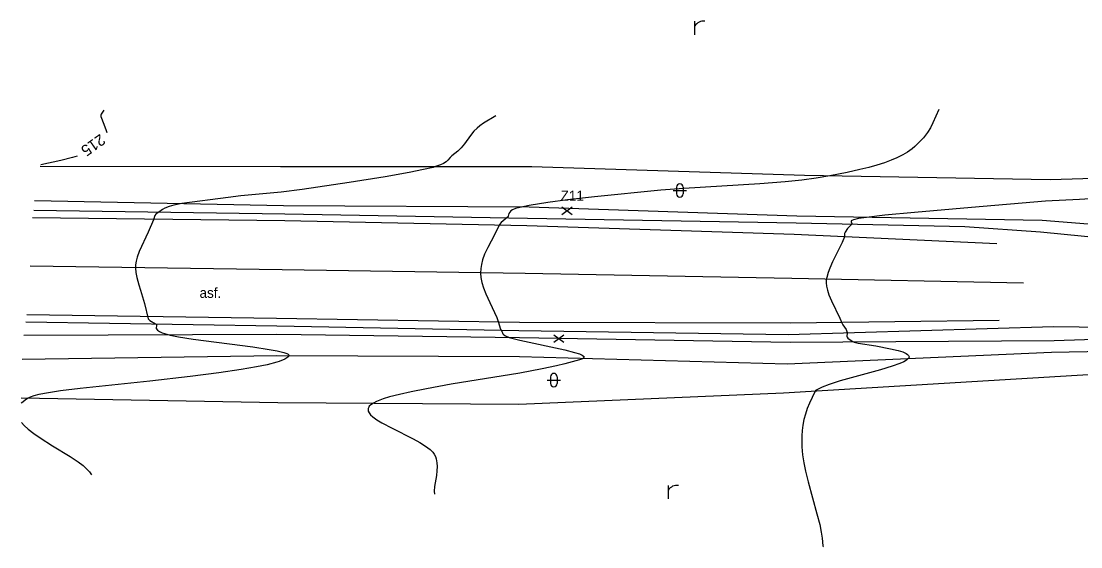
# Model space of a CAD drawing. Extents: x -593772 to -592667, y -1183541 to -1183371.
# Drawn here: x -593771.8 to -593692.9, y -1183410.3 to -1183371.1 of the extents above; entities that cross this region are included whole.
import ezdxf

# ---------------------------------------------------------------- set-up
doc = ezdxf.new("R2010")
doc.units = 0
for name, color, linetype in [('bez obruby', 7, 'Continuous'), ('hlavni vrstevnice', 7, 'Continuous'), ('popis ploch', 7, 'Continuous'), ('svisle dopravni znaceni', 7, 'Continuous'), ('terenni hrany', 7, 'Continuous'), ('vodorovne dopravni znaceni', 7, 'Continuous'), ('vrstevnice', 7, 'Continuous')]:
    doc.layers.add(name, color=color, linetype=linetype)

msp = doc.modelspace()

# ---------------------------------------------------------------- linework, layer by layer
at = {"layer": 'bez obruby'}
for p, q in [((-593752.18, -1183385.49), (-593770.88, -1183385.22)), ((-593734.08, -1183385.82), (-593752.18, -1183385.49)), ((-593714.07, -1183386.17), (-593734.08, -1183385.82)), ((-593701.52, -1183386.44), (-593714.07, -1183386.17)), ((-593695.87, -1183386.84), (-593701.52, -1183386.44)), ((-593688.93, -1183387.52), (-593695.87, -1183386.84)), ((-593752.76, -1183393.84), (-593771.46, -1183393.55)), ((-593734.75, -1183394.2), (-593752.76, -1183393.84)), ((-593694.9, -1183393.91), (-593714.68, -1183394.5)), ((-593678.82, -1183394.05), (-593694.9, -1183393.91)), ((-593714.68, -1183394.5), (-593734.75, -1183394.2))]:
    msp.add_line(p, q, dxfattribs=at)
at = {"layer": 'hlavni vrstevnice'}
for points in [[(-593765.643, -1183377.754), (-593765.843, -1183378.037), (-593765.873, -1183378.123), (-593765.874, -1183378.214), (-593765.836, -1183378.355), (-593765.707, -1183378.662), (-593765.5, -1183379.195), (-593765.441, -1183379.411)], [(-593767.646, -1183381.184), (-593767.992, -1183381.282), (-593768.866, -1183381.496), (-593770.357, -1183381.812)]]:
    msp.add_lwpolyline(points, dxfattribs=at)
at = {"layer": 'popis ploch'}
for p, q in [((-593721.63, -1183372.12), (-593721.63, -1183371.12)), ((-593723.24, -1183383.74), (-593722.24, -1183383.74)), ((-593722.99, -1183383.49), (-593722.99, -1183383.99)), ((-593722.49, -1183383.49), (-593722.49, -1183383.99)), ((-593732.63, -1183397.87), (-593731.63, -1183397.87)), ((-593732.38, -1183397.62), (-593732.38, -1183398.12)), ((-593731.88, -1183397.62), (-593731.88, -1183398.12)), ((-593723.6, -1183406.73), (-593723.6, -1183405.73))]:
    msp.add_line(p, q, dxfattribs=at)
for centre, radius, start, end in [((-593720.993, -1183371.857), 0.746, 81.32683, 148.70696), ((-593722.741, -1183383.49), 0.25, 0, 180), ((-593722.741, -1183383.99), 0.25, 180, 0), ((-593732.131, -1183397.62), 0.25, 0, 180), ((-593732.131, -1183398.12), 0.25, 180, 0), ((-593722.963, -1183406.468), 0.746, 81.32683, 148.70696)]:
    msp.add_arc(centre, radius, start, end, dxfattribs=at)
at = {"layer": 'svisle dopravni znaceni'}
for p, q in [((-593731.525, -1183385.521), (-593730.775, -1183384.958)), ((-593731.525, -1183384.958), (-593730.775, -1183385.521)), ((-593732.125, -1183395.051), (-593731.375, -1183394.488)), ((-593732.125, -1183394.488), (-593731.375, -1183395.051))]:
    msp.add_line(p, q, dxfattribs=at)
at = {"layer": 'terenni hrany'}
for p, q in [((-593752.49, -1183381.97), (-593770.39, -1183381.95)), ((-593733.78, -1183381.98), (-593752.49, -1183381.97)), ((-593713.46, -1183382.62), (-593733.78, -1183381.98)), ((-593695.15, -1183382.93), (-593713.46, -1183382.62)), ((-593678.75, -1183382.47), (-593695.15, -1183382.93)), ((-593752.26, -1183384.88), (-593770.82, -1183384.5)), ((-593733.97, -1183384.97), (-593752.26, -1183384.88)), ((-593714.04, -1183385.64), (-593733.97, -1183384.97)), ((-593695.76, -1183385.98), (-593714.04, -1183385.64)), ((-593678.56, -1183387.34), (-593695.76, -1183385.98)), ((-593752.76, -1183394.47), (-593771.61, -1183394.56)), ((-593734.7, -1183394.71), (-593752.76, -1183394.47)), ((-593714.52, -1183395.08), (-593734.7, -1183394.71)), ((-593678.83, -1183394.43), (-593694.86, -1183394.94)), ((-593694.86, -1183394.94), (-593714.52, -1183395.08)), ((-593678.91, -1183395.57), (-593695.06, -1183395.81)), ((-593752.77, -1183396.07), (-593771.73, -1183396.33)), ((-593734.68, -1183396.15), (-593752.77, -1183396.07)), ((-593714.74, -1183396.69), (-593734.68, -1183396.15)), ((-593695.06, -1183395.81), (-593714.74, -1183396.69)), ((-593684.31, -1183397), (-593715.02, -1183398.85)), ((-593752.7, -1183399.56), (-593771.81, -1183399.21)), ((-593734.75, -1183399.68), (-593752.7, -1183399.56)), ((-593715.02, -1183398.85), (-593734.75, -1183399.68))]:
    msp.add_line(p, q, dxfattribs=at)
at = {"layer": 'vodorovne dopravni znaceni'}
for p, q in [((-593752.16, -1183386.01), (-593770.97, -1183385.78)), ((-593734.14, -1183386.36), (-593752.16, -1183386.01)), ((-593714.22, -1183387.02), (-593734.14, -1183386.36)), ((-593699.14, -1183387.71), (-593714.22, -1183387.02)), ((-593752.37, -1183389.65), (-593771.15, -1183389.39)), ((-593734.26, -1183389.93), (-593752.37, -1183389.65)), ((-593714.41, -1183390.29), (-593734.26, -1183389.93)), ((-593697.15, -1183390.64), (-593714.41, -1183390.29)), ((-593752.78, -1183393.27), (-593771.4, -1183393.01)), ((-593734.7, -1183393.59), (-593752.78, -1183393.27)), ((-593714.49, -1183393.63), (-593734.7, -1183393.59)), ((-593698.96, -1183393.44), (-593714.49, -1183393.63))]:
    msp.add_line(p, q, dxfattribs=at)
at = {"layer": 'vrstevnice'}
for points in [[(-593736.445, -1183378.178), (-593737.379, -1183378.725), (-593737.649, -1183378.912), (-593737.847, -1183379.078), (-593738.091, -1183379.323), (-593738.339, -1183379.633), (-593738.779, -1183380.25), (-593739.038, -1183380.555), (-593739.29, -1183380.799), (-593739.723, -1183381.149), (-593739.847, -1183381.272), (-593740.021, -1183381.481), (-593740.159, -1183381.609), (-593740.343, -1183381.727), (-593740.572, -1183381.832), (-593740.941, -1183381.958), (-593741.128, -1183382.01), (-593741.829, -1183382.178), (-593742.915, -1183382.398), (-593744.693, -1183382.713), (-593747.378, -1183383.141), (-593750.867, -1183383.654), (-593752.444, -1183383.866), (-593755.439, -1183384.139), (-593756.385, -1183384.247), (-593759.846, -1183384.717), (-593760.433, -1183384.822), (-593760.779, -1183384.919), (-593761.1, -1183385.049), (-593761.271, -1183385.151), (-593761.56, -1183385.363), (-593761.78, -1183385.504), (-593761.861, -1183385.597), (-593761.962, -1183385.912), (-593762.361, -1183386.846), (-593763.014, -1183388.293), (-593763.165, -1183388.698), (-593763.246, -1183388.993), (-593763.294, -1183389.29), (-593763.303, -1183389.532), (-593763.277, -1183389.839), (-593763.203, -1183390.214), (-593763.039, -1183390.78), (-593762.919, -1183391.161), (-593762.63, -1183392.168), (-593762.339, -1183393.294), (-593762.288, -1183393.372), (-593762.232, -1183393.42), (-593761.798, -1183393.668), (-593761.756, -1183393.707), (-593761.727, -1183393.76), (-593761.73, -1183393.833), (-593761.764, -1183393.969), (-593761.744, -1183394.035), (-593761.661, -1183394.138), (-593761.519, -1183394.244), (-593761.297, -1183394.349), (-593760.972, -1183394.456), (-593760.718, -1183394.519), (-593760.09, -1183394.642), (-593758.99, -1183394.811), (-593754.559, -1183395.391), (-593753.328, -1183395.581), (-593752.75, -1183395.69), (-593752.236, -1183395.813), (-593752.03, -1183395.885), (-593751.926, -1183395.936), (-593751.862, -1183395.988), (-593751.84, -1183396.037), (-593751.845, -1183396.061), (-593751.94, -1183396.166), (-593752.161, -1183396.306), (-593752.585, -1183396.476), (-593752.757, -1183396.536), (-593753.484, -1183396.723), (-593754.29, -1183396.889), (-593755.417, -1183397.083), (-593757.098, -1183397.328), (-593759.219, -1183397.597), (-593762.224, -1183397.944), (-593767.405, -1183398.489), (-593768.871, -1183398.674), (-593769.786, -1183398.817), (-593770.507, -1183398.958), (-593770.873, -1183399.053), (-593771.145, -1183399.147), (-593771.285, -1183399.212), (-593771.496, -1183399.351), (-593771.695, -1183399.507), (-593771.804, -1183399.602)], [(-593703.459, -1183377.701), (-593703.888, -1183378.68), (-593704.081, -1183379.054), (-593704.306, -1183379.416), (-593704.602, -1183379.8), (-593705.007, -1183380.242), (-593705.229, -1183380.45), (-593705.441, -1183380.626), (-593705.784, -1183380.869), (-593706.139, -1183381.08), (-593706.569, -1183381.296), (-593706.997, -1183381.477), (-593707.503, -1183381.663), (-593708.061, -1183381.842), (-593708.671, -1183382.015), (-593709.331, -1183382.182), (-593710.276, -1183382.394), (-593711.578, -1183382.655), (-593712.579, -1183382.821), (-593713.645, -1183382.967), (-593714.891, -1183383.09), (-593716.782, -1183383.233), (-593722.438, -1183383.578), (-593724.166, -1183383.72), (-593729.096, -1183384.208), (-593731.113, -1183384.441), (-593732.574, -1183384.638), (-593733.98, -1183384.867), (-593734.666, -1183385.001), (-593734.988, -1183385.088), (-593735.205, -1183385.176), (-593735.339, -1183385.26), (-593735.419, -1183385.346), (-593735.473, -1183385.459), (-593735.531, -1183385.658), (-593735.597, -1183385.757), (-593736.062, -1183386.133), (-593736.172, -1183386.265), (-593736.563, -1183387.037), (-593737.057, -1183387.984), (-593737.286, -1183388.493), (-593737.433, -1183388.896), (-593737.526, -1183389.244), (-593737.572, -1183389.544), (-593737.584, -1183389.91), (-593737.558, -1183390.221), (-593737.484, -1183390.601), (-593737.371, -1183390.986), (-593737.199, -1183391.437), (-593736.902, -1183392.093), (-593736.384, -1183393.206), (-593736.248, -1183393.567), (-593736.127, -1183394.01), (-593736.071, -1183394.134), (-593736.016, -1183394.227), (-593735.938, -1183394.414), (-593735.865, -1183394.498), (-593735.736, -1183394.583), (-593735.455, -1183394.694), (-593735.25, -1183394.754), (-593734.661, -1183394.895), (-593731.303, -1183395.62), (-593730.591, -1183395.806), (-593730.222, -1183395.927), (-593730.009, -1183396.025), (-593729.916, -1183396.091), (-593729.883, -1183396.141), (-593729.885, -1183396.189), (-593729.921, -1183396.235), (-593729.992, -1183396.279), (-593730.223, -1183396.366), (-593731.304, -1183396.656), (-593731.928, -1183396.815), (-593732.991, -1183397.042), (-593734.654, -1183397.349), (-593739.777, -1183398.186), (-593741.614, -1183398.515), (-593742.77, -1183398.746), (-593743.623, -1183398.937), (-593744.366, -1183399.13), (-593744.855, -1183399.281), (-593745.345, -1183399.47), (-593745.568, -1183399.581), (-593745.762, -1183399.71), (-593745.878, -1183399.823), (-593745.918, -1183399.879), (-593745.969, -1183400), (-593745.972, -1183400.128), (-593745.956, -1183400.19), (-593745.892, -1183400.323), (-593745.781, -1183400.463), (-593745.622, -1183400.61), (-593745.323, -1183400.828), (-593744.953, -1183401.054), (-593744.181, -1183401.464), (-593742.607, -1183402.251), (-593742.104, -1183402.527), (-593741.68, -1183402.796), (-593741.348, -1183403.056), (-593741.151, -1183403.257), (-593741.038, -1183403.407), (-593740.949, -1183403.574), (-593740.897, -1183403.733), (-593740.844, -1183404.046), (-593740.826, -1183404.305), (-593740.838, -1183404.639), (-593740.88, -1183404.987), (-593741.022, -1183405.811), (-593741.047, -1183406.147), (-593741.027, -1183406.39)], [(-593691.791, -1183384.34), (-593692.965, -1183384.416), (-593695.51, -1183384.54), (-593701.027, -1183384.993), (-593705.272, -1183385.366), (-593707.465, -1183385.587), (-593708.827, -1183385.744), (-593709.422, -1183385.833), (-593709.812, -1183385.918), (-593709.929, -1183385.966), (-593709.972, -1183386.008), (-593709.978, -1183386.061), (-593709.928, -1183386.196), (-593709.938, -1183386.24), (-593710.243, -1183386.576), (-593710.434, -1183386.846), (-593710.466, -1183386.95), (-593710.479, -1183387.181), (-593710.657, -1183387.612), (-593711.379, -1183389.067), (-593711.57, -1183389.515), (-593711.687, -1183389.846), (-593711.805, -1183390.211), (-593711.835, -1183390.367), (-593711.844, -1183390.614), (-593711.814, -1183390.872), (-593711.75, -1183391.158), (-593711.638, -1183391.504), (-593711.443, -1183391.971), (-593710.825, -1183393.255), (-593710.684, -1183393.593), (-593710.593, -1183393.761), (-593710.362, -1183394.111), (-593710.269, -1183394.328), (-593710.271, -1183394.372), (-593710.311, -1183394.589), (-593710.291, -1183394.676), (-593710.237, -1183394.752), (-593709.915, -1183394.978), (-593709.749, -1183395.05), (-593709.47, -1183395.114), (-593708.134, -1183395.323), (-593707.041, -1183395.532), (-593706.488, -1183395.664), (-593706.138, -1183395.772), (-593705.894, -1183395.879), (-593705.774, -1183395.958), (-593705.699, -1183396.039), (-593705.676, -1183396.092), (-593705.671, -1183396.146), (-593705.695, -1183396.226), (-593705.751, -1183396.299), (-593705.848, -1183396.381), (-593706.062, -1183396.506), (-593706.361, -1183396.638), (-593706.928, -1183396.843), (-593707.799, -1183397.108), (-593710.788, -1183397.931), (-593711.631, -1183398.195), (-593712.14, -1183398.391), (-593712.53, -1183398.588), (-593712.629, -1183398.66), (-593712.691, -1183398.74), (-593713.09, -1183399.589), (-593713.257, -1183400.001), (-593713.393, -1183400.411), (-593713.501, -1183400.819), (-593713.58, -1183401.225), (-593713.632, -1183401.63), (-593713.661, -1183402.034), (-593713.667, -1183402.437), (-593713.652, -1183402.839), (-593713.596, -1183403.448), (-593713.507, -1183404.045), (-593713.385, -1183404.657), (-593713.192, -1183405.461), (-593712.527, -1183407.847), (-593712.327, -1183408.651), (-593712.215, -1183409.203), (-593712.143, -1183409.65), (-593712.08, -1183410.236), (-593712.057, -1183410.286), (-593712.04, -1183410.304)], [(-593771.782, -1183401.039), (-593771.59, -1183401.25), (-593771.287, -1183401.527), (-593770.88, -1183401.845), (-593770.387, -1183402.187), (-593769.472, -1183402.764), (-593768.154, -1183403.574), (-593767.558, -1183403.971), (-593767.198, -1183404.244), (-593766.908, -1183404.505), (-593766.712, -1183404.725), (-593766.566, -1183404.938)]]:
    msp.add_lwpolyline(points, dxfattribs=at)

# ---------------------------------------------------------------- texts
at = {"layer": 'hlavni vrstevnice'}
msp.add_text('215', height=0.8351, rotation=215.40235, dxfattribs=at).set_placement((-593765.922, -1183379.484))
at = {"layer": 'popis ploch'}
msp.add_text('asf.', height=0.75, dxfattribs=at).set_placement((-593758.523, -1183391.74))
at = {"layer": 'svisle dopravni znaceni'}
msp.add_text('Z11', height=0.75, dxfattribs=at).set_placement((-593731.624, -1183384.5))

doc.saveas('drawing.dxf')
